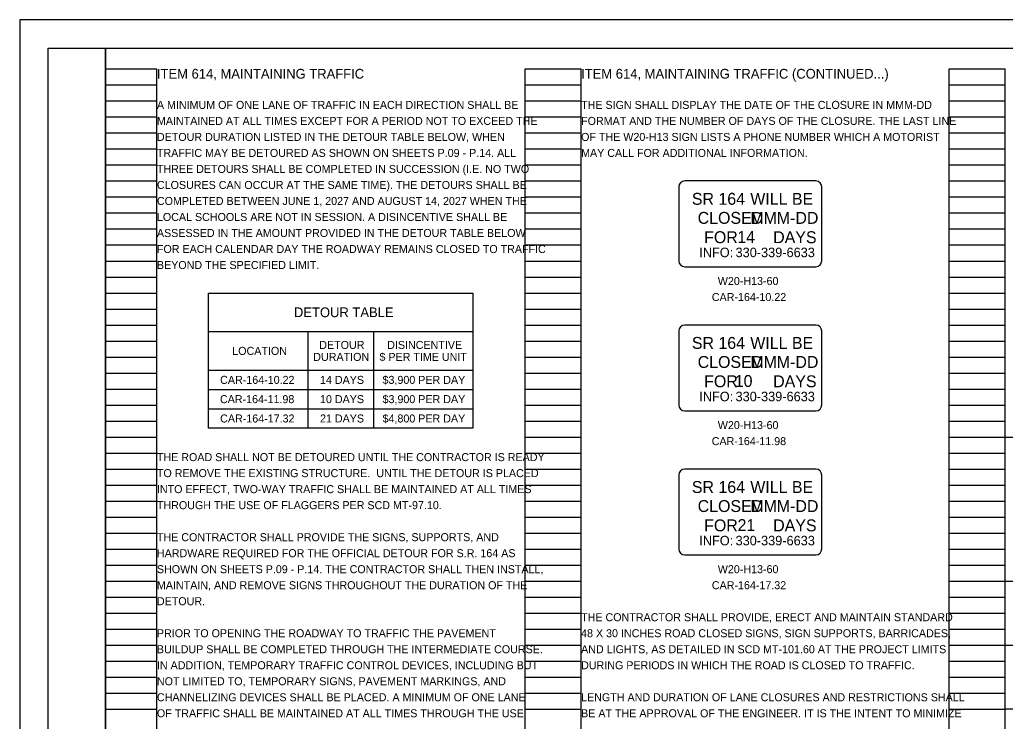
# Model space of a CAD drawing. Extents: x 0 to 34, y -10.1 to 22.
# Drawn here: x 0 to 17.24, y 9.73 to 22 of the extents above; entities that cross this region are included whole.
import ezdxf

# ---------------------------------------------------------------- set-up
doc = ezdxf.new("R2010")
doc.units = 0
for name, color, linetype in [('SH_Border', 7, 'Continuous'), ('SH_Cut_Line', 7, 'Continuous'), ('SH_Data', 7, 'Continuous'), ('SH_Text', 7, 'Continuous'), ('SN_P_Signs', 7, 'Continuous'), ('SN_P_Text', 7, 'Continuous')]:
    doc.layers.add(name, color=color, linetype=linetype)

msp = doc.modelspace()

# ---------------------------------------------------------------- linework, layer by layer
at = {"layer": 'SH_Border'}
for points in [[(0.5, 21.5), (1.5, 21.5), (1.5, 0.5), (0.5, 0.5)], [(1.5, 21.5), (33.5, 21.5), (33.5, 0.5), (1.5, 0.5)]]:
    msp.add_lwpolyline(points, close=True, dxfattribs=at)
at = {"layer": 'SH_Cut_Line'}
msp.add_lwpolyline([(0, 0), (34, 0), (34, 22), (0, 22)], close=True, dxfattribs=at)
at = {"layer": 'SH_Data'}
for p, q in [((1.5, 0.98), (1.5, 21.14)), ((1.5, 21.14), (2.4, 21.14)), ((2.4, 0.98), (2.4, 21.14)), ((8.84, 0.98), (8.84, 21.14)), ((8.84, 21.14), (9.82, 21.14)), ((9.82, 0.98), (9.82, 21.14)), ((16.26, 0.98), (16.26, 21.14)), ((16.26, 21.14), (17.24, 21.14)), ((17.24, 0.98), (17.24, 21.14)), ((1.5, 20.86), (2.4, 20.86)), ((8.84, 20.86), (9.82, 20.86)), ((16.26, 20.86), (17.24, 20.86)), ((1.5, 20.58), (2.4, 20.58)), ((8.84, 20.58), (9.82, 20.58)), ((16.26, 20.58), (17.24, 20.58)), ((1.5, 20.3), (2.4, 20.3)), ((8.84, 20.3), (9.82, 20.3)), ((16.26, 20.3), (17.24, 20.3)), ((1.5, 20.02), (2.4, 20.02)), ((8.84, 20.02), (9.82, 20.02)), ((16.26, 20.02), (17.24, 20.02)), ((1.5, 19.74), (2.4, 19.74)), ((8.84, 19.74), (9.82, 19.74)), ((16.26, 19.74), (17.24, 19.74)), ((1.5, 19.46), (2.4, 19.46)), ((8.84, 19.46), (9.82, 19.46)), ((16.26, 19.46), (17.24, 19.46)), ((1.5, 19.18), (2.4, 19.18)), ((8.84, 19.18), (9.82, 19.18)), ((16.26, 19.18), (17.24, 19.18)), ((1.5, 18.9), (2.4, 18.9)), ((8.84, 18.9), (9.82, 18.9)), ((16.26, 18.9), (17.24, 18.9)), ((1.5, 18.62), (2.4, 18.62)), ((8.84, 18.62), (9.82, 18.62)), ((16.26, 18.62), (17.24, 18.62)), ((1.5, 18.34), (2.4, 18.34)), ((8.84, 18.34), (9.82, 18.34)), ((16.26, 18.34), (17.24, 18.34)), ((1.5, 18.06), (2.4, 18.06)), ((8.84, 18.06), (9.82, 18.06)), ((16.26, 18.06), (17.24, 18.06)), ((1.5, 17.78), (2.4, 17.78)), ((8.84, 17.78), (9.82, 17.78)), ((16.26, 17.78), (17.24, 17.78)), ((1.5, 17.5), (2.4, 17.5)), ((8.84, 17.5), (9.82, 17.5)), ((16.26, 17.5), (17.24, 17.5)), ((1.5, 17.22), (2.4, 17.22)), ((8.84, 17.22), (9.82, 17.22)), ((16.26, 17.22), (17.24, 17.22)), ((1.5, 16.94), (2.4, 16.94)), ((8.84, 16.94), (9.82, 16.94)), ((16.26, 16.94), (17.24, 16.94)), ((1.5, 16.66), (2.4, 16.66)), ((8.84, 16.66), (9.82, 16.66)), ((16.26, 16.66), (17.24, 16.66)), ((1.5, 16.38), (2.4, 16.38)), ((8.84, 16.38), (9.82, 16.38)), ((16.26, 16.38), (17.24, 16.38)), ((1.5, 16.1), (2.4, 16.1)), ((8.84, 16.1), (9.82, 16.1)), ((16.26, 16.1), (17.24, 16.1)), ((1.5, 15.82), (2.4, 15.82)), ((8.84, 15.82), (9.82, 15.82)), ((16.26, 15.82), (17.24, 15.82)), ((1.5, 15.54), (2.4, 15.54)), ((8.84, 15.54), (9.82, 15.54)), ((16.26, 15.54), (17.24, 15.54)), ((1.5, 15.26), (2.4, 15.26)), ((8.84, 15.26), (9.82, 15.26)), ((16.26, 15.26), (17.24, 15.26)), ((1.5, 14.98), (2.4, 14.98)), ((8.84, 14.98), (9.82, 14.98)), ((16.26, 14.98), (17.24, 14.98)), ((1.5, 14.7), (2.4, 14.7)), ((8.84, 14.7), (9.82, 14.7)), ((16.26, 14.7), (17.24, 14.7)), ((1.5, 14.42), (2.4, 14.42)), ((8.84, 14.42), (9.82, 14.42)), ((16.26, 14.42), (17.24, 14.42)), ((1.5, 14.14), (2.4, 14.14)), ((8.84, 14.14), (9.82, 14.14)), ((16.26, 14.14), (17.24, 14.14)), ((1.5, 13.86), (2.4, 13.86)), ((8.84, 13.86), (9.82, 13.86)), ((16.26, 13.86), (17.24, 13.86)), ((1.5, 13.58), (2.4, 13.58)), ((8.84, 13.58), (9.82, 13.58)), ((16.26, 13.58), (17.24, 13.58)), ((1.5, 13.3), (2.4, 13.3)), ((8.84, 13.3), (9.82, 13.3)), ((16.26, 13.3), (17.24, 13.3)), ((1.5, 13.02), (2.4, 13.02)), ((8.84, 13.02), (9.82, 13.02)), ((16.26, 13.02), (17.24, 13.02)), ((1.5, 12.74), (2.4, 12.74)), ((8.84, 12.74), (9.82, 12.74)), ((16.26, 12.74), (17.24, 12.74)), ((1.5, 12.46), (2.4, 12.46)), ((8.84, 12.46), (9.82, 12.46)), ((16.26, 12.46), (17.24, 12.46)), ((1.5, 12.18), (2.4, 12.18)), ((8.84, 12.18), (9.82, 12.18)), ((16.26, 12.18), (17.24, 12.18)), ((1.5, 11.9), (2.4, 11.9)), ((8.84, 11.9), (9.82, 11.9)), ((16.26, 11.9), (17.24, 11.9)), ((1.5, 11.62), (2.4, 11.62)), ((8.84, 11.62), (9.82, 11.62)), ((16.26, 11.62), (17.24, 11.62)), ((1.5, 11.34), (2.4, 11.34)), ((8.84, 11.34), (9.82, 11.34)), ((16.26, 11.34), (17.24, 11.34)), ((1.5, 11.06), (2.4, 11.06)), ((8.84, 11.06), (9.82, 11.06)), ((16.26, 11.06), (17.24, 11.06)), ((1.5, 10.78), (2.4, 10.78)), ((8.84, 10.78), (9.82, 10.78)), ((16.26, 10.78), (17.24, 10.78)), ((1.5, 10.5), (2.4, 10.5)), ((8.84, 10.5), (9.82, 10.5)), ((16.26, 10.5), (17.24, 10.5)), ((1.5, 10.22), (2.4, 10.22)), ((8.84, 10.22), (9.82, 10.22)), ((16.26, 10.22), (17.24, 10.22)), ((1.5, 9.94), (2.4, 9.94)), ((8.84, 9.94), (9.82, 9.94)), ((16.26, 9.94), (17.24, 9.94))]:
    msp.add_line(p, q, dxfattribs=at)
at = {"layer": 'SH_Text'}
for p, q in [((3.301, 17.22), (7.924, 17.22)), ((3.301, 14.858), (3.301, 17.22)), ((7.924, 17.22), (7.924, 14.858)), ((3.301, 16.545), (7.924, 16.545)), ((5.039, 16.545), (5.039, 14.858)), ((6.186, 16.545), (6.186, 14.858)), ((3.301, 15.87), (7.924, 15.87)), ((3.301, 15.533), (7.924, 15.533)), ((3.301, 15.195), (7.924, 15.195)), ((7.924, 14.858), (3.301, 14.858)), ((17.24, 12.18), (23.68, 12.18)), ((17.24, 11.06), (23.68, 11.06))]:
    msp.add_line(p, q, dxfattribs=at)
msp.add_lwpolyline([(17.24, 14.7), (23.68, 14.7), (23.68, 9.94), (17.24, 9.94)], close=True, dxfattribs=at)
at = {"layer": 'SN_P_Signs'}
for p, q in [((13.926, 19.18), (11.634, 19.18)), ((11.53, 19.076), (11.53, 17.784)), ((14.03, 17.784), (14.03, 19.076)), ((11.634, 17.68), (13.926, 17.68)), ((11.53, 16.556), (11.53, 15.264)), ((13.926, 16.66), (11.634, 16.66)), ((14.03, 15.264), (14.03, 16.556)), ((11.634, 15.16), (13.926, 15.16)), ((13.926, 14.14), (11.634, 14.14)), ((11.53, 14.036), (11.53, 12.744)), ((14.03, 12.744), (14.03, 14.036)), ((11.634, 12.64), (13.926, 12.64))]:
    msp.add_line(p, q, dxfattribs=at)
for centre, start, end in [((11.634, 19.076), 90, 180), ((13.926, 19.076), 0, 90), ((11.634, 17.784), 180, 270), ((13.926, 17.784), 270, 360), ((11.634, 16.556), 90, 180), ((13.926, 16.556), 0, 90), ((11.634, 15.264), 180, 270), ((13.926, 15.264), 270, 360), ((11.634, 14.036), 90, 180), ((13.926, 14.036), 0, 90), ((11.634, 12.744), 180, 270), ((13.926, 12.744), 270, 360)]:
    msp.add_arc(centre, 0.104, start, end, dxfattribs=at)

# ---------------------------------------------------------------- texts
at = {"layer": 'SH_Text'}
for s, height, p in [('ITEM 614, MAINTAINING TRAFFIC ', 0.17, (2.4, 20.97)), ('ITEM 614, MAINTAINING TRAFFIC (CONTINUED...)', 0.17, (9.82, 20.97)), ('A MINIMUM OF ONE LANE OF TRAFFIC IN EACH DIRECTION SHALL BE ', 0.14, (2.4, 20.44)), ('THE SIGN SHALL DISPLAY THE DATE OF THE CLOSURE IN MMM-DD ', 0.14, (9.82, 20.44)), ('MAINTAINED AT ALL TIMES EXCEPT FOR A PERIOD NOT TO EXCEED THE  ', 0.14, (2.4, 20.16)), ('FORMAT AND THE NUMBER OF DAYS OF THE CLOSURE. THE LAST LINE ', 0.14, (9.82, 20.16)), ('DETOUR DURATION LISTED IN THE DETOUR TABLE BELOW, WHEN ', 0.14, (2.4, 19.88)), ('OF THE W20-H13 SIGN LISTS A PHONE NUMBER WHICH A MOTORIST ', 0.14, (9.82, 19.88)), ('TRAFFIC MAY BE DETOURED AS SHOWN ON SHEETS P.09 - P.14. ALL ', 0.14, (2.4, 19.6)), ('MAY CALL FOR ADDITIONAL INFORMATION. ', 0.14, (9.82, 19.6)), ('THREE DETOURS SHALL BE COMPLETED IN SUCCESSION (I.E. NO TWO ', 0.14, (2.4, 19.32)), ('CLOSURES CAN OCCUR AT THE SAME TIME). THE DETOURS SHALL BE ', 0.14, (2.4, 19.04)), ('COMPLETED BETWEEN JUNE 1, 2027 AND AUGUST 14, 2027 WHEN THE ', 0.14, (2.4, 18.76)), ('LOCAL SCHOOLS ARE NOT IN SESSION. A DISINCENTIVE SHALL BE ', 0.14, (2.4, 18.48)), ('ASSESSED IN THE AMOUNT PROVIDED IN THE DETOUR TABLE BELOW ', 0.14, (2.4, 18.2)), ('FOR EACH CALENDAR DAY THE ROADWAY REMAINS CLOSED TO TRAFFIC ', 0.14, (2.4, 17.92)), ('BEYOND THE SPECIFIED LIMIT.', 0.14, (2.4, 17.64)), ('DETOUR TABLE', 0.17, (4.797, 16.798)), ('DETOUR ', 0.14, (5.24, 16.242)), ('DISINCENTIVE', 0.14, (6.428, 16.242)), ('LOCATION', 0.14, (3.718, 16.138)), ('DURATION', 0.14, (5.135, 16.033)), ('$ PER TIME UNIT', 0.14, (6.293, 16.033)), ('CAR-164-10.22', 0.14, (3.506, 15.631)), ('14 DAYS', 0.14, (5.253, 15.631)), ('$3,900 PER DAY', 0.14, (6.347, 15.631)), ('CAR-164-11.98', 0.14, (3.503, 15.294)), ('10 DAYS', 0.14, (5.253, 15.294)), ('$3,900 PER DAY', 0.14, (6.347, 15.294)), ('CAR-164-17.32', 0.14, (3.506, 14.956)), ('21 DAYS', 0.14, (5.253, 14.956)), ('$4,800 PER DAY', 0.14, (6.347, 14.956)), ('THE ROAD SHALL NOT BE DETOURED UNTIL THE CONTRACTOR IS READY ', 0.14, (2.4, 14.28)), ('TO REMOVE THE EXISTING STRUCTURE.  UNTIL THE DETOUR IS PLACED ', 0.14, (2.4, 14)), ('INTO EFFECT, TWO-WAY TRAFFIC SHALL BE MAINTAINED AT ALL TIMES ', 0.14, (2.4, 13.72)), ('THROUGH THE USE OF FLAGGERS PER SCD MT-97.10.', 0.14, (2.4, 13.44)), ('THE CONTRACTOR SHALL PROVIDE THE SIGNS, SUPPORTS, AND ', 0.14, (2.4, 12.88)), ('HARDWARE REQUIRED FOR THE OFFICIAL DETOUR FOR S.R. 164 AS ', 0.14, (2.4, 12.6)), ('SHOWN ON SHEETS P.09 - P.14. THE CONTRACTOR SHALL THEN INSTALL, ', 0.14, (2.4, 12.32)), ('MAINTAIN, AND REMOVE SIGNS THROUGHOUT THE DURATION OF THE ', 0.14, (2.4, 12.04)), ('DETOUR.', 0.14, (2.4, 11.76)), ('THE CONTRACTOR SHALL PROVIDE, ERECT AND MAINTAIN STANDARD ', 0.14, (9.82, 11.48)), ('PRIOR TO OPENING THE ROADWAY TO TRAFFIC THE PAVEMENT ', 0.14, (2.4, 11.2)), ('48 X 30 INCHES ROAD CLOSED SIGNS, SIGN SUPPORTS, BARRICADES, ', 0.14, (9.82, 11.2)), ('BUILDUP SHALL BE COMPLETED THROUGH THE INTERMEDIATE COURSE. ', 0.14, (2.4, 10.92)), ('AND LIGHTS, AS DETAILED IN SCD MT-101.60 AT THE PROJECT LIMITS ', 0.14, (9.82, 10.92)), ('IN ADDITION, TEMPORARY TRAFFIC CONTROL DEVICES, INCLUDING BUT ', 0.14, (2.4, 10.64)), ('DURING PERIODS IN WHICH THE ROAD IS CLOSED TO TRAFFIC. ', 0.14, (9.82, 10.64)), ('NOT LIMITED TO, TEMPORARY SIGNS, PAVEMENT MARKINGS, AND ', 0.14, (2.4, 10.36)), ('CHANNELIZING DEVICES SHALL BE PLACED. A MINIMUM OF ONE LANE ', 0.14, (2.4, 10.08)), ('LENGTH AND DURATION OF LANE CLOSURES AND RESTRICTIONS SHALL ', 0.14, (9.82, 10.08)), ('OF TRAFFIC SHALL BE MAINTAINED AT ALL TIMES THROUGH THE USE  ', 0.14, (2.4, 9.8)), ('BE AT THE APPROVAL OF THE ENGINEER. IT IS THE INTENT TO MINIMIZE ', 0.14, (9.82, 9.8))]:
    msp.add_text(s, height=height, dxfattribs=at).set_placement(p)
at = {"layer": 'SN_P_Signs'}
for s, height, p in [('  SR 164', 0.2083, (11.603, 18.763)), ('WILL BE', 0.2083, (12.78, 18.763)), (' CLOSED', 0.2083, (11.782, 18.43)), ('MMM-DD', 0.2083, (12.78, 18.43)), ('  FOR        DAYS', 0.20833, (11.818, 18.092)), ('  14', 0.2083, (12.398, 18.097)), ('  INFO:', 0.1666, (11.763, 17.847)), (' 330-339-6633', 0.16658, (12.46, 17.847)), ('  SR 164', 0.2083, (11.603, 16.243)), ('WILL BE', 0.2083, (12.78, 16.243)), (' CLOSED', 0.2083, (11.782, 15.91)), ('MMM-DD', 0.2083, (12.78, 15.91)), ('  FOR        DAYS', 0.20833, (11.818, 15.572)), (' 10', 0.2083, (12.431, 15.577)), ('  INFO:', 0.1666, (11.763, 15.327)), (' 330-339-6633', 0.16658, (12.46, 15.327)), ('  SR 164', 0.2083, (11.603, 13.723)), ('WILL BE', 0.2083, (12.78, 13.723)), (' CLOSED', 0.2083, (11.782, 13.39)), ('MMM-DD', 0.2083, (12.78, 13.39)), ('  FOR        DAYS', 0.20833, (11.818, 13.052)), ('  21', 0.2083, (12.402, 13.057)), ('  INFO:', 0.1666, (11.763, 12.807)), (' 330-339-6633', 0.16658, (12.46, 12.807))]:
    msp.add_text(s, height=height, dxfattribs=at).set_placement(p)
at = {"layer": 'SN_P_Text'}
for s, p in [('W20-H13-60', (12.211, 17.36)), ('CAR-164-10.22', (12.107, 17.08)), ('W20-H13-60', (12.211, 14.84)), ('CAR-164-11.98', (12.105, 14.56)), ('W20-H13-60', (12.211, 12.32)), ('CAR-164-17.32', (12.107, 12.04))]:
    msp.add_text(s, height=0.14, dxfattribs=at).set_placement(p)

doc.saveas('drawing.dxf')
